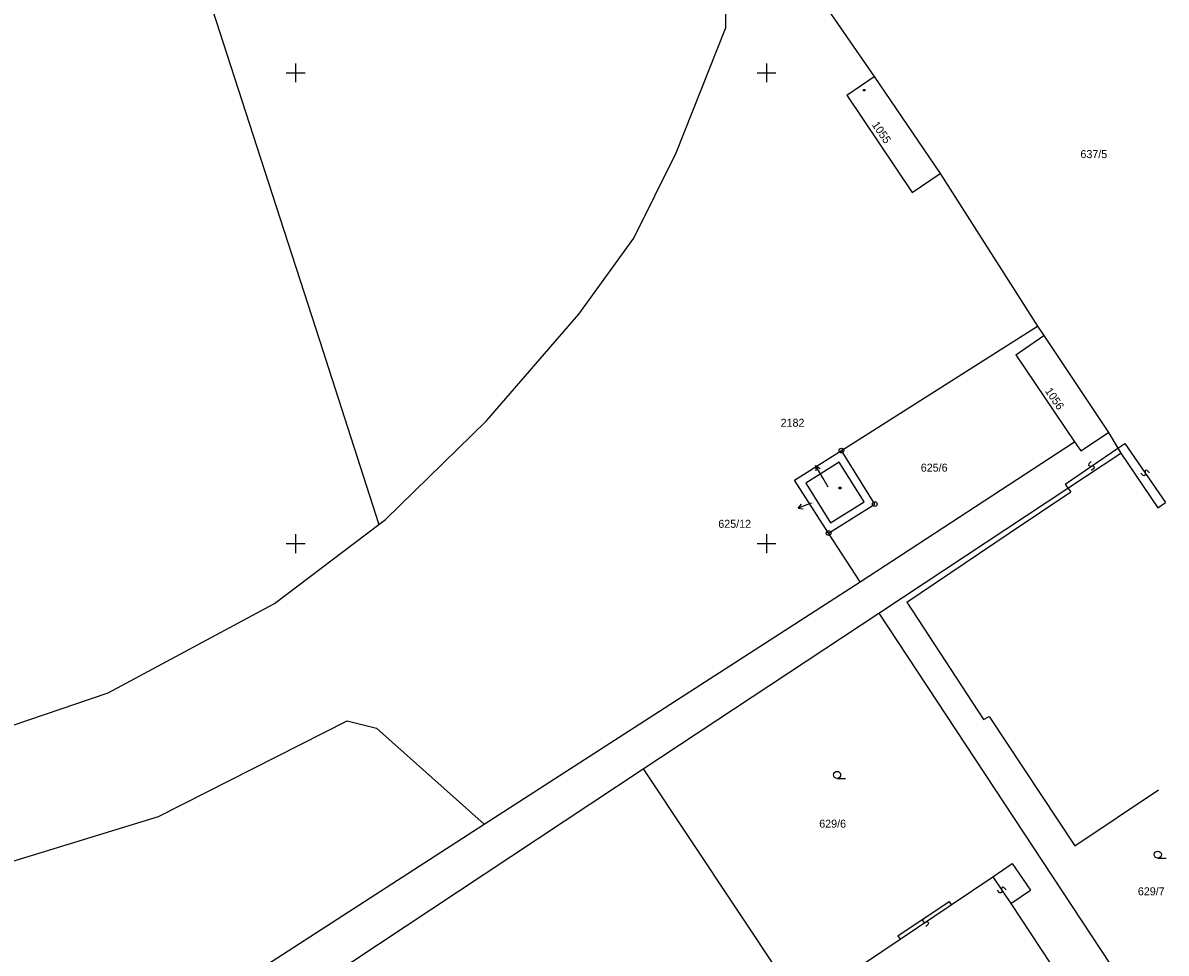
# Model space of a CAD drawing. Extents: x -493352 to -492964, y -1127001 to -1126712.
# Drawn here: x -493037.4 to -492964.5, y -1126916.1 to -1126856.8 of the extents above; entities that cross this region are included whole.
import ezdxf

# ---------------------------------------------------------------- set-up
doc = ezdxf.new("R2010")
doc.units = 0
doc.layers.add('katastrální mapa', color=7, linetype='Continuous')
doc.layers.add('síť', color=7, linetype='Continuous')

msp = doc.modelspace()

# ---------------------------------------------------------------- linework, layer by layer
at = {"layer": 'katastrální mapa'}
for p, q in [((-493026.71, -1126851.57), (-493022.46, -1126864.72)), ((-492988.76, -1126852.06), (-492983.15, -1126860.22)), ((-492992.62, -1126854.58), (-492992.61, -1126857.17)), ((-492995.76, -1126865.09), (-492992.61, -1126857.17)), ((-492984.89, -1126861.41), (-492983.15, -1126860.22)), ((-492983.15, -1126860.22), (-492978.93, -1126866.42)), ((-492984.89, -1126861.41), (-492980.73, -1126867.63)), ((-492983.82, -1126861.06), (-492983.73, -1126861.06)), ((-492983.82, -1126861.15), (-492983.82, -1126861.06)), ((-492983.73, -1126861.15), (-492983.82, -1126861.15)), ((-492983.73, -1126861.06), (-492983.73, -1126861.15)), ((-493022.46, -1126864.72), (-493020, -1126872.32)), ((-492998.45, -1126870.53), (-492995.76, -1126865.09)), ((-492980.73, -1126867.63), (-492978.93, -1126866.42)), ((-492978.93, -1126866.42), (-492972.74, -1126876.14)), ((-493001.96, -1126875.38), (-492998.45, -1126870.53)), ((-493020, -1126872.32), (-493019.7, -1126873.22)), ((-493019.7, -1126873.22), (-493018.47, -1126877.04)), ((-493007.84, -1126882.17), (-493001.96, -1126875.38)), ((-492985.23, -1126884.07), (-492972.74, -1126876.14)), ((-492972.74, -1126876.14), (-492972.33, -1126876.74)), ((-492974.11, -1126877.96), (-492972.33, -1126876.74)), ((-492972.33, -1126876.74), (-492968.22, -1126882.91)), ((-493018.47, -1126877.04), (-493014.7, -1126888.78)), ((-492974.11, -1126877.96), (-492970.38, -1126883.52)), ((-493014.28, -1126888.46), (-493007.84, -1126882.17)), ((-492969.97, -1126884.09), (-492968.22, -1126882.91)), ((-492968.22, -1126882.91), (-492967.62, -1126883.91)), ((-492988.22, -1126885.96), (-492985.23, -1126884.07)), ((-492983.1, -1126887.48), (-492985.23, -1126884.07)), ((-492984.03, -1126892.43), (-492970.38, -1126883.52)), ((-492970.98, -1126886.2), (-492967.62, -1126883.91)), ((-492970.38, -1126883.52), (-492969.97, -1126884.09)), ((-492967.62, -1126883.91), (-492967.17, -1126883.61)), ((-492967.62, -1126883.91), (-492967.43, -1126884.23)), ((-492967.17, -1126883.61), (-492964.58, -1126887.38)), ((-492985.36, -1126884.81), (-492987.49, -1126886.15)), ((-492983.78, -1126887.33), (-492985.36, -1126884.81)), ((-492970.81, -1126886.46), (-492967.43, -1126884.23)), ((-492969.31, -1126884.77), (-492969.47, -1126884.92)), ((-492967.43, -1126884.23), (-492965.06, -1126887.71)), ((-492986.42, -1126885.8), (-492986.87, -1126885.02)), ((-492986.87, -1126885.02), (-492986.85, -1126885.36)), ((-492986.87, -1126885.02), (-492986.59, -1126885.21)), ((-492969.47, -1126884.92), (-492969.48, -1126885)), ((-492969.48, -1126885), (-492969.45, -1126885.05)), ((-492969.45, -1126885.05), (-492969.37, -1126885.06)), ((-492969.37, -1126885.06), (-492969.23, -1126885.05)), ((-492969.13, -1126885.19), (-492969.29, -1126885.34)), ((-492969.23, -1126885.05), (-492969.15, -1126885.06)), ((-492969.15, -1126885.06), (-492969.12, -1126885.11)), ((-492969.12, -1126885.11), (-492969.13, -1126885.19)), ((-492966.01, -1126885.66), (-492966.16, -1126885.51)), ((-492965.87, -1126885.35), (-492965.88, -1126885.43)), ((-492965.88, -1126885.43), (-492965.87, -1126885.56)), ((-492965.87, -1126885.56), (-492965.88, -1126885.64)), ((-492965.82, -1126885.31), (-492965.87, -1126885.35)), ((-492965.74, -1126885.33), (-492965.82, -1126885.31)), ((-492965.59, -1126885.48), (-492965.74, -1126885.33)), ((-492986.04, -1126889.33), (-492988.22, -1126885.96)), ((-492987.49, -1126886.15), (-492985.92, -1126888.67)), ((-492986.08, -1126886.39), (-492986.42, -1126885.8)), ((-492970.98, -1126886.2), (-492970.81, -1126886.46)), ((-492965.93, -1126885.68), (-492966.01, -1126885.66)), ((-492965.88, -1126885.64), (-492965.93, -1126885.68)), ((-492985.36, -1126886.41), (-492985.27, -1126886.41)), ((-492985.36, -1126886.5), (-492985.36, -1126886.41)), ((-492985.27, -1126886.5), (-492985.36, -1126886.5)), ((-492985.27, -1126886.41), (-492985.27, -1126886.5)), ((-492981.27, -1126893.39), (-492970.81, -1126886.46)), ((-492974.54, -1126889.33), (-492970.62, -1126886.7)), ((-492970.81, -1126886.46), (-492970.62, -1126886.7)), ((-492987.15, -1126887.42), (-492987.99, -1126887.74)), ((-492987.99, -1126887.74), (-492987.76, -1126887.49)), ((-492987.99, -1126887.74), (-492987.66, -1126887.77)), ((-492986.04, -1126889.33), (-492983.1, -1126887.48)), ((-492985.92, -1126888.67), (-492983.78, -1126887.33)), ((-492965.06, -1126887.71), (-492964.58, -1126887.38)), ((-493014.7, -1126888.78), (-493014.28, -1126888.46)), ((-493021.34, -1126893.81), (-493014.7, -1126888.78)), ((-492984.03, -1126892.43), (-492986.04, -1126889.33)), ((-492981.05, -1126893.72), (-492974.54, -1126889.33)), ((-493007.98, -1126907.88), (-492984.03, -1126892.43)), ((-492982.85, -1126894.43), (-492981.27, -1126893.39)), ((-493031.94, -1126899.51), (-493021.34, -1126893.81)), ((-492981.05, -1126893.72), (-492976.17, -1126901.21)), ((-492997.86, -1126904.36), (-492982.85, -1126894.43)), ((-492982.85, -1126894.43), (-492966.34, -1126919.47)), ((-493040.34, -1126902.35), (-493031.94, -1126899.51)), ((-493028.74, -1126907.38), (-493016.72, -1126901.3)), ((-493016.72, -1126901.3), (-493014.85, -1126901.75)), ((-492976.17, -1126901.21), (-492975.82, -1126901.02)), ((-492975.82, -1126901.02), (-492970.35, -1126909.25)), ((-493014.85, -1126901.75), (-493008.77, -1126907.17)), ((-493036.12, -1126929.67), (-492997.86, -1126904.36)), ((-492997.86, -1126904.36), (-492984.51, -1126924.39)), ((-492985.5, -1126904.96), (-492984.97, -1126904.96)), ((-492970.35, -1126909.25), (-492965.03, -1126905.69)), ((-493038.63, -1126910.42), (-493028.74, -1126907.38)), ((-493008.77, -1126907.17), (-493007.98, -1126907.88)), ((-493063.66, -1126943.8), (-493007.98, -1126907.88)), ((-492975.58, -1126911.23), (-492974.34, -1126910.39)), ((-492974.34, -1126910.39), (-492973.19, -1126912.09)), ((-492965.07, -1126910.04), (-492964.54, -1126910.04)), ((-492978.23, -1126913.01), (-492975.58, -1126911.23)), ((-492975.58, -1126911.23), (-492974.44, -1126912.93)), ((-492975.15, -1126912.25), (-492975.29, -1126912.09)), ((-492975.07, -1126912.26), (-492975.15, -1126912.25)), ((-492975.02, -1126912.23), (-492975.07, -1126912.26)), ((-492975, -1126911.93), (-492975.02, -1126912.01)), ((-492975.02, -1126912.01), (-492975, -1126912.15)), ((-492975, -1126912.15), (-492975.02, -1126912.23)), ((-492974.95, -1126911.9), (-492975, -1126911.93)), ((-492974.87, -1126911.91), (-492974.95, -1126911.9)), ((-492974.73, -1126912.07), (-492974.87, -1126911.91)), ((-492974.44, -1126912.93), (-492973.19, -1126912.09)), ((-492981.63, -1126915), (-492978.37, -1126912.81)), ((-492981.49, -1126915.21), (-492978.23, -1126913.01)), ((-492978.37, -1126912.81), (-492978.23, -1126913.01)), ((-492974.44, -1126912.93), (-492968.97, -1126921.22)), ((-492980.03, -1126913.97), (-492980.04, -1126914.05)), ((-492979.87, -1126913.83), (-492980.03, -1126913.97)), ((-492980.04, -1126914.05), (-492980.01, -1126914.1)), ((-492980.01, -1126914.1), (-492979.93, -1126914.12)), ((-492979.93, -1126914.12), (-492979.79, -1126914.1)), ((-492979.69, -1126914.25), (-492979.85, -1126914.39)), ((-492979.79, -1126914.1), (-492979.71, -1126914.12)), ((-492979.71, -1126914.12), (-492979.68, -1126914.17)), ((-492979.68, -1126914.17), (-492979.69, -1126914.25)), ((-492984.93, -1126917.52), (-492981.49, -1126915.21)), ((-492981.63, -1126915), (-492981.49, -1126915.21))]:
    msp.add_line(p, q, dxfattribs=at)
for centre, radius in [((-492985.23, -1126884.07), 0.15), ((-492985.23, -1126884.07), 0.003), ((-492983.1, -1126887.48), 0.15), ((-492983.1, -1126887.48), 0.003), ((-492986.04, -1126889.33), 0.15), ((-492986.04, -1126889.33), 0.003), ((-492985.5, -1126904.735), 0.225), ((-492965.07, -1126909.815), 0.225)]:
    msp.add_circle(centre, radius, dxfattribs=at)
at = {"layer": 'síť'}
for p, q in [((-493020, -1126859.4), (-493020, -1126860.6)), ((-492990, -1126859.4), (-492990, -1126860.6)), ((-493020.6, -1126860), (-493019.4, -1126860)), ((-492990.6, -1126860), (-492989.4, -1126860)), ((-493020.6, -1126890), (-493019.4, -1126890)), ((-493020, -1126889.4), (-493020, -1126890.6)), ((-492990.6, -1126890), (-492989.4, -1126890)), ((-492990, -1126889.4), (-492990, -1126890.6))]:
    msp.add_line(p, q, dxfattribs=at)

# ---------------------------------------------------------------- texts
at = {"layer": 'katastrální mapa'}
for s, rotation, p in [('1055', 304.641, (-492983.31, -1126863.31)), ('1056', 304.128, (-492972.28, -1126880.27))]:
    msp.add_text(s, height=0.51, rotation=rotation, dxfattribs=at).set_placement(p)
for s, height, p in [('637/5', 0.51, (-492970, -1126865.43)), ('2182', 0.51, (-492989.1, -1126882.55)), ('625/6', 0.51, (-492980.17, -1126885.41)), ('2182', 0.03, (-492986.08, -1126886.39)), ('625/12', 0.03, (-492987.15, -1126887.42)), ('625/12', 0.51, (-492993.07, -1126888.99)), ('629/6', 0.51, (-492986.64, -1126908.1)), ('629/7', 0.51, (-492966.34, -1126912.41))]:
    msp.add_text(s, height=height, dxfattribs=at).set_placement(p)

doc.saveas('drawing.dxf')
